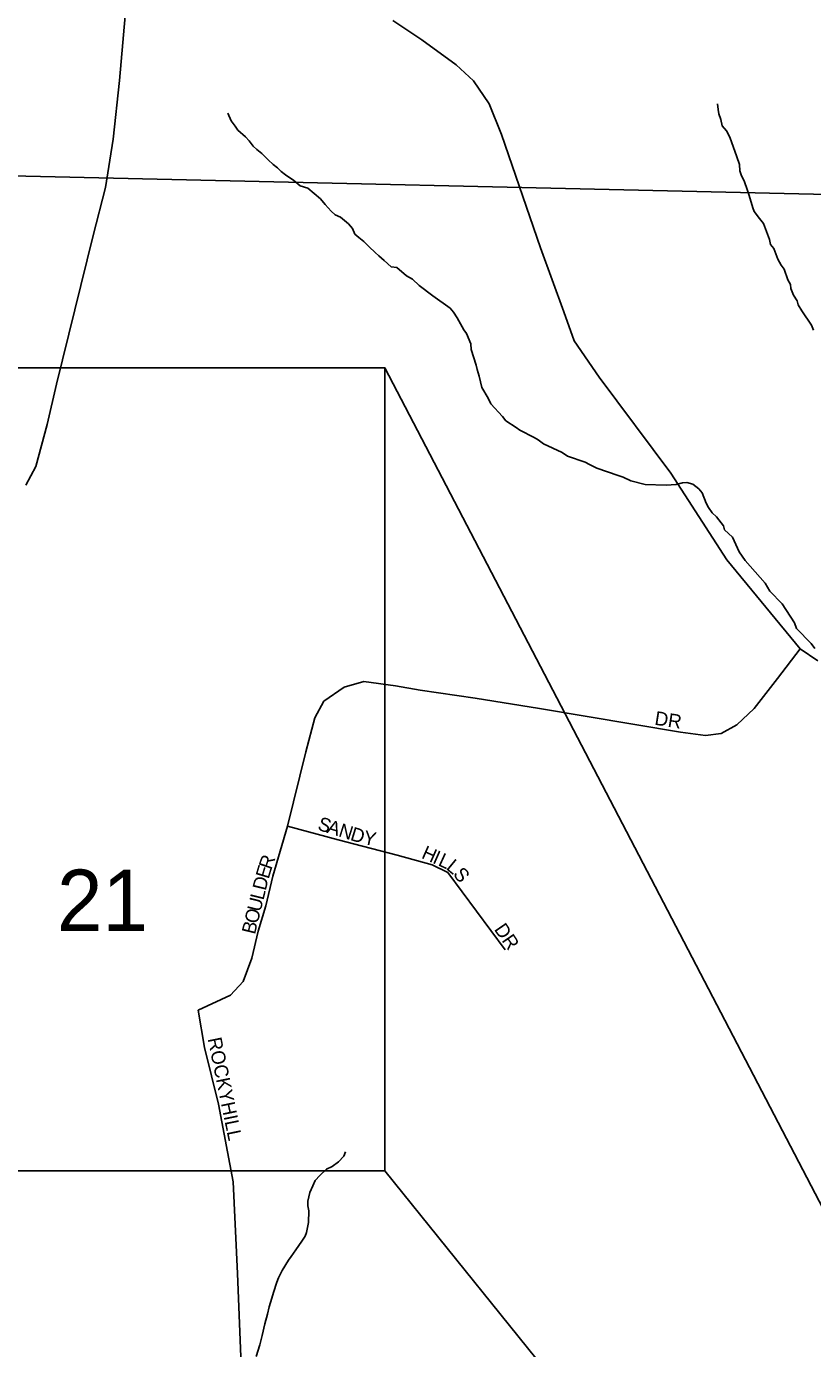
# Model space of a CAD drawing. Extents: x 0 to 34, y -2.3 to 22.
# Drawn here: x 4.776 to 5.313, y 16.564 to 17.468 of the extents above; entities that cross this region are included whole.
import ezdxf

# ---------------------------------------------------------------- set-up
doc = ezdxf.new("R2010")
doc.units = 0
for name, color, linetype in [('GM_X_County_Road', 7, 'Continuous'), ('GM_X_Minor_River', 7, 'Continuous'), ('GM_X_Section', 7, 'Continuous'), ('GM_X_Section_Text', 7, 'Continuous'), ('GM_X_Township_Road', 7, 'Continuous'), ('GM_X_Township_Subdivision', 7, 'Continuous'), ('GM_X_Township_Subdivision_Text', 7, 'Continuous'), ('SH_Text', 7, 'Continuous')]:
    doc.layers.add(name, color=color, linetype=linetype)

msp = doc.modelspace()

# ---------------------------------------------------------------- linework, layer by layer
at = {"layer": 'GM_X_County_Road'}
for p, q in [((4.83936, 17.43078), (4.84738, 17.51912)), ((4.83516, 17.39055), (4.83936, 17.43078)), ((4.82981, 17.3577), (4.83516, 17.39055)), ((4.82141, 17.32472), (4.82981, 17.3577)), ((4.79646, 17.22312), (4.82141, 17.32472)), ((4.79009, 17.19562), (4.79646, 17.22312)), ((4.78219, 17.16684), (4.79009, 17.19562)), ((4.77545, 17.15411), (4.78219, 17.16684))]:
    msp.add_line(p, q, dxfattribs=at)
at = {"layer": 'GM_X_Minor_River'}
for p, q in [((4.9157, 17.40309), (4.91357, 17.40847)), ((5.2489, 17.41097), (5.24825, 17.41478)), ((5.24919, 17.40792), (5.2489, 17.41097)), ((5.2506, 17.40408), (5.24919, 17.40792)), ((4.91864, 17.39958), (4.9157, 17.40309)), ((4.92046, 17.39687), (4.91864, 17.39958)), ((5.25162, 17.39987), (5.2506, 17.40408)), ((5.25456, 17.39636), (5.25162, 17.39987)), ((4.92564, 17.39216), (4.92046, 17.39687)), ((4.92822, 17.38942), (4.92564, 17.39216)), ((4.93078, 17.38592), (4.92822, 17.38942)), ((5.25671, 17.39212), (5.25456, 17.39636)), ((5.26164, 17.37868), (5.25671, 17.39212)), ((4.93337, 17.38357), (4.93078, 17.38592)), ((4.93671, 17.38081), (4.93337, 17.38357)), ((4.94115, 17.3765), (4.93671, 17.38081)), ((4.94448, 17.37336), (4.94115, 17.3765)), ((4.94745, 17.37099), (4.94448, 17.37336)), ((4.95004, 17.36863), (4.94745, 17.37099)), ((5.26339, 17.37331), (5.26164, 17.37868)), ((5.26364, 17.36912), (5.26339, 17.37331)), ((4.95301, 17.36627), (4.95004, 17.36863)), ((4.9586, 17.3623), (4.95301, 17.36627)), ((4.96306, 17.35875), (4.9586, 17.3623)), ((5.26468, 17.36567), (5.26364, 17.36912)), ((5.26648, 17.3622), (5.26468, 17.36567)), ((5.26895, 17.35567), (5.26648, 17.3622)), ((4.96833, 17.35707), (4.96306, 17.35875)), ((4.97687, 17.34998), (4.96833, 17.35707)), ((5.26999, 17.35222), (5.26895, 17.35567)), ((4.98017, 17.34608), (4.97687, 17.34998)), ((4.98422, 17.3414), (4.98017, 17.34608)), ((5.27241, 17.34379), (5.26999, 17.35222)), ((5.27347, 17.3411), (5.27241, 17.34379)), ((4.98681, 17.33904), (4.98422, 17.3414)), ((4.99056, 17.33741), (4.98681, 17.33904)), ((4.99613, 17.33269), (4.99056, 17.33741)), ((5.27714, 17.33643), (5.27347, 17.3411)), ((5.27969, 17.33293), (5.27714, 17.33643)), ((4.9987, 17.32957), (4.99613, 17.33269)), ((5.00048, 17.32572), (4.9987, 17.32957)), ((5.00308, 17.32336), (5.00048, 17.32572)), ((5.28394, 17.32217), (5.27969, 17.33293)), ((5.00642, 17.3206), (5.00308, 17.32336)), ((5.01012, 17.31707), (5.00642, 17.3206)), ((5.01418, 17.31315), (5.01012, 17.31707)), ((5.2846, 17.31873), (5.28394, 17.32217)), ((5.2868, 17.31601), (5.2846, 17.31873)), ((5.01677, 17.3108), (5.01418, 17.31315)), ((5.02048, 17.30765), (5.01677, 17.3108)), ((5.0253, 17.30332), (5.02048, 17.30765)), ((5.28963, 17.30871), (5.2868, 17.31601)), ((5.29179, 17.30446), (5.28963, 17.30871)), ((5.02909, 17.30283), (5.0253, 17.30332)), ((5.03577, 17.29732), (5.02909, 17.30283)), ((5.29399, 17.30174), (5.29179, 17.30446)), ((5.29643, 17.29445), (5.29399, 17.30174)), ((5.03988, 17.29491), (5.03577, 17.29732)), ((5.04431, 17.2906), (5.03988, 17.29491)), ((5.05361, 17.28349), (5.04431, 17.2906)), ((5.29825, 17.29135), (5.29643, 17.29445)), ((5.29855, 17.28869), (5.29825, 17.29135)), ((5.06553, 17.27515), (5.05361, 17.28349)), ((5.30031, 17.28407), (5.29855, 17.28869)), ((5.30286, 17.2802), (5.30031, 17.28407)), ((5.30354, 17.27752), (5.30286, 17.2802)), ((5.06773, 17.27243), (5.06553, 17.27515)), ((5.07028, 17.26855), (5.06773, 17.27243)), ((5.30608, 17.27327), (5.30354, 17.27752)), ((5.31264, 17.26357), (5.30608, 17.27327)), ((5.07498, 17.26043), (5.07028, 17.26855)), ((5.31406, 17.26011), (5.31264, 17.26357)), ((5.0768, 17.25772), (5.07498, 17.26043)), ((5.07964, 17.2508), (5.0768, 17.25772)), ((5.07991, 17.24699), (5.07964, 17.2508)), ((5.0834, 17.23625), (5.07991, 17.24699)), ((5.08407, 17.23319), (5.0834, 17.23625)), ((5.08546, 17.22859), (5.08407, 17.23319)), ((5.08714, 17.22094), (5.08546, 17.22859)), ((5.09148, 17.2136), (5.08714, 17.22094)), ((5.09327, 17.20975), (5.09148, 17.2136)), ((5.10138, 17.20115), (5.09327, 17.20975)), ((5.10357, 17.19804), (5.10138, 17.20115)), ((5.11067, 17.19365), (5.10357, 17.19804)), ((5.11327, 17.19167), (5.11067, 17.19365)), ((5.12301, 17.18682), (5.11327, 17.19167)), ((5.12562, 17.18523), (5.12301, 17.18682)), ((5.12934, 17.18246), (5.12562, 17.18523)), ((5.14209, 17.17638), (5.12934, 17.18246)), ((5.14582, 17.17399), (5.14209, 17.17638)), ((5.15786, 17.16983), (5.14582, 17.17399)), ((5.16086, 17.16822), (5.15786, 17.16983)), ((5.16573, 17.16579), (5.16086, 17.16822)), ((5.18041, 17.16079), (5.16573, 17.16579)), ((5.18379, 17.15955), (5.18041, 17.16079)), ((5.18904, 17.15712), (5.18379, 17.15955)), ((5.19885, 17.15454), (5.18904, 17.15712)), ((5.21328, 17.15411), (5.19885, 17.15454)), ((5.22014, 17.15467), (5.21328, 17.15411)), ((5.22435, 17.15568), (5.22014, 17.15467)), ((5.2274, 17.15597), (5.22435, 17.15568)), ((5.23154, 17.15471), (5.2274, 17.15597)), ((5.23563, 17.15154), (5.23154, 17.15471)), ((5.23783, 17.14882), (5.23563, 17.15154)), ((5.24067, 17.1419), (5.23783, 17.14882)), ((5.2421, 17.13882), (5.24067, 17.1419)), ((5.24466, 17.13532), (5.2421, 17.13882)), ((5.24762, 17.13257), (5.24466, 17.13532)), ((5.25238, 17.12635), (5.24762, 17.13257)), ((5.25307, 17.12367), (5.25238, 17.12635)), ((5.25862, 17.11857), (5.25307, 17.12367)), ((5.26327, 17.10855), (5.25862, 17.11857)), ((5.26728, 17.10274), (5.26327, 17.10855)), ((5.28089, 17.08713), (5.26728, 17.10274)), ((5.28415, 17.08172), (5.28089, 17.08713)), ((5.29264, 17.07311), (5.28415, 17.08172)), ((5.301, 17.05994), (5.29264, 17.07311)), ((5.30241, 17.0561), (5.301, 17.05994)), ((5.31238, 17.04593), (5.30241, 17.0561)), ((5.31493, 17.04243), (5.31238, 17.04593)), ((4.98923, 16.69169), (4.99276, 16.69539)), ((4.99276, 16.69539), (4.99398, 16.69839)), ((4.97641, 16.6822), (4.9811, 16.68662)), ((4.9811, 16.68662), (4.98495, 16.6884)), ((4.98495, 16.6884), (4.98923, 16.69169)), ((4.96961, 16.67063), (4.97164, 16.67513)), ((4.97164, 16.67513), (4.97327, 16.67888)), ((4.97327, 16.67888), (4.97641, 16.6822)), ((4.96829, 16.66459), (4.96961, 16.67063)), ((4.96821, 16.66155), (4.96829, 16.66459)), ((4.96886, 16.65811), (4.96821, 16.66155)), ((4.96863, 16.65014), (4.96886, 16.65811)), ((4.96729, 16.64335), (4.96863, 16.65014)), ((4.96408, 16.63736), (4.96646, 16.64071)), ((4.96646, 16.64071), (4.96729, 16.64335)), ((4.95693, 16.62694), (4.9601, 16.6314)), ((4.9601, 16.6314), (4.96408, 16.63736)), ((4.95057, 16.61726), (4.95496, 16.62434)), ((4.95496, 16.62434), (4.95693, 16.62694)), ((4.94692, 16.60939), (4.94815, 16.61239)), ((4.94815, 16.61239), (4.95057, 16.61726)), ((4.94356, 16.59847), (4.94481, 16.60223)), ((4.94481, 16.60223), (4.94692, 16.60939)), ((4.94187, 16.59244), (4.94356, 16.59847)), ((4.93886, 16.58076), (4.94058, 16.58754)), ((4.94058, 16.58754), (4.94187, 16.59244)), ((4.93711, 16.57283), (4.93886, 16.58076)), ((4.93289, 16.55853), (4.93541, 16.56643)), ((4.93541, 16.56643), (4.93711, 16.57283))]:
    msp.add_line(p, q, dxfattribs=at)
at = {"layer": 'GM_X_Section'}
for p, q in [((5.3441, 17.35232), (4.33847, 17.37521)), ((4.33847, 17.37521), (5.3441, 17.35232))]:
    msp.add_line(p, q, dxfattribs=at)
at = {"layer": 'GM_X_Township_Road'}
for p, q in [((5.04621, 17.45861), (5.02646, 17.47173)), ((5.06965, 17.44158), (5.04621, 17.45861)), ((5.08158, 17.4306), (5.06965, 17.44158)), ((5.09231, 17.4147), (5.08158, 17.4306)), ((5.10055, 17.39391), (5.09231, 17.4147)), ((5.1273, 17.3163), (5.10055, 17.39391)), ((5.14318, 17.27272), (5.1273, 17.3163)), ((5.15041, 17.2529), (5.14318, 17.27272)), ((5.16754, 17.22806), (5.15041, 17.2529)), ((5.21636, 17.16224), (5.16754, 17.22806)), ((5.25472, 17.1032), (5.21636, 17.16224)), ((5.30478, 17.04235), (5.25472, 17.1032)), ((5.31686, 17.03396), (5.30478, 17.04235))]:
    msp.add_line(p, q, dxfattribs=at)
at = {"layer": 'GM_X_Township_Subdivision'}
for p, q in [((5.30478, 17.04235), (5.28936, 17.02197)), ((5.00659, 17.01985), (4.99302, 17.01616)), ((5.0281, 17.01703), (5.00659, 17.01985)), ((5.28936, 17.02197), (5.27331, 17.00152)), ((4.99302, 17.01616), (4.97927, 17.00646)), ((5.04502, 17.01404), (5.0281, 17.01703)), ((5.08257, 17.00858), (5.04502, 17.01404)), ((4.97927, 17.00646), (4.9731, 16.995)), ((5.12665, 17.00152), (5.08257, 17.00858)), ((5.22308, 16.98531), (5.12665, 17.00152)), ((5.27331, 17.00152), (5.2615, 16.99041)), ((4.9731, 16.995), (4.96693, 16.97191)), ((5.24018, 16.98301), (5.22308, 16.98531)), ((5.25093, 16.98442), (5.24018, 16.98301)), ((5.2615, 16.99041), (5.25093, 16.98442)), ((4.96693, 16.97191), (4.95441, 16.92096)), ((4.95441, 16.92096), (4.94419, 16.88676)), ((4.95441, 16.92096), (4.98896, 16.91179)), ((4.98896, 16.91179), (5.00553, 16.90739)), ((5.00553, 16.90739), (5.02933, 16.90122)), ((5.02933, 16.90122), (5.05331, 16.89469)), ((5.05331, 16.89469), (5.06406, 16.8894)), ((4.94419, 16.88676), (4.93943, 16.86666)), ((5.06406, 16.8894), (5.10319, 16.83652)), ((4.93943, 16.86666), (4.93428, 16.84915)), ((4.93428, 16.84915), (4.9299, 16.83086)), ((4.9299, 16.83086), (4.92394, 16.81496)), ((4.92394, 16.81496), (4.91539, 16.80541)), ((4.91539, 16.80541), (4.89333, 16.79528)), ((4.89333, 16.79528), (4.89758, 16.76971)), ((4.89758, 16.76971), (4.90704, 16.73107)), ((4.90704, 16.73107), (4.91718, 16.67799)), ((4.91718, 16.67799), (4.92016, 16.61517)), ((4.92016, 16.61517), (4.92294, 16.54679))]:
    msp.add_line(p, q, dxfattribs=at)
at = {"layer": 'SH_Text'}
for points in [[(3.1803, 17.23424), (5.02099, 17.23424), (5.02099, 16.68544), (3.1803, 16.68544)], [(5.02099, 16.68544), (5.83077, 15.68102), (5.02099, 17.23424)], [(5.02099, 16.68544), (5.02099, 17.23424), (5.83077, 15.68102)]]:
    msp.add_lwpolyline(points, close=True, dxfattribs=at)

# ---------------------------------------------------------------- texts
at = {"layer": 'GM_X_Section_Text'}
msp.add_text('21', height=0.041856, rotation=0.00001, dxfattribs=at).set_placement((4.79672, 16.84946))
at = {"layer": 'GM_X_Township_Subdivision_Text'}
for s, rotation, p in [('DR', 351.02664, (5.20492, 16.99043)), ('S', 342.53271, (4.97435, 16.9187)), ('A', 342.52928, (4.9807, 16.9167)), ('N', 342.53337, (4.98865, 16.9142)), ('D', 343.18204, (4.99671, 16.91166)), ('Y', 348.17636, (5.00557, 16.90903)), ('R', 70.72599, (4.94327, 16.89078)), ('H', 336.15069, (5.04534, 16.89948)), ('I', 336.17049, (5.05296, 16.89611)), ('L', 335.34125, (5.05674, 16.89444)), ('E', 73.27589, (4.94139, 16.88451)), ('L', 320.56786, (5.06225, 16.892)), ('S', 309.11639, (5.06705, 16.88812)), ('D', 76.144, (4.93942, 16.87654)), ('L', 76.20972, (4.93784, 16.87006)), ('O', 76.20228, (4.93386, 16.85388)), ('U', 76.20021, (4.93585, 16.86197)), ('B', 76.20527, (4.93207, 16.8466)), ('DR', 304.50969, (5.09527, 16.85051)), ('ROCKYHILL', 281.59203, (4.89972, 16.77571))]:
    msp.add_text(s, height=0.00947, rotation=rotation, dxfattribs=at).set_placement(p)

doc.saveas('drawing.dxf')
